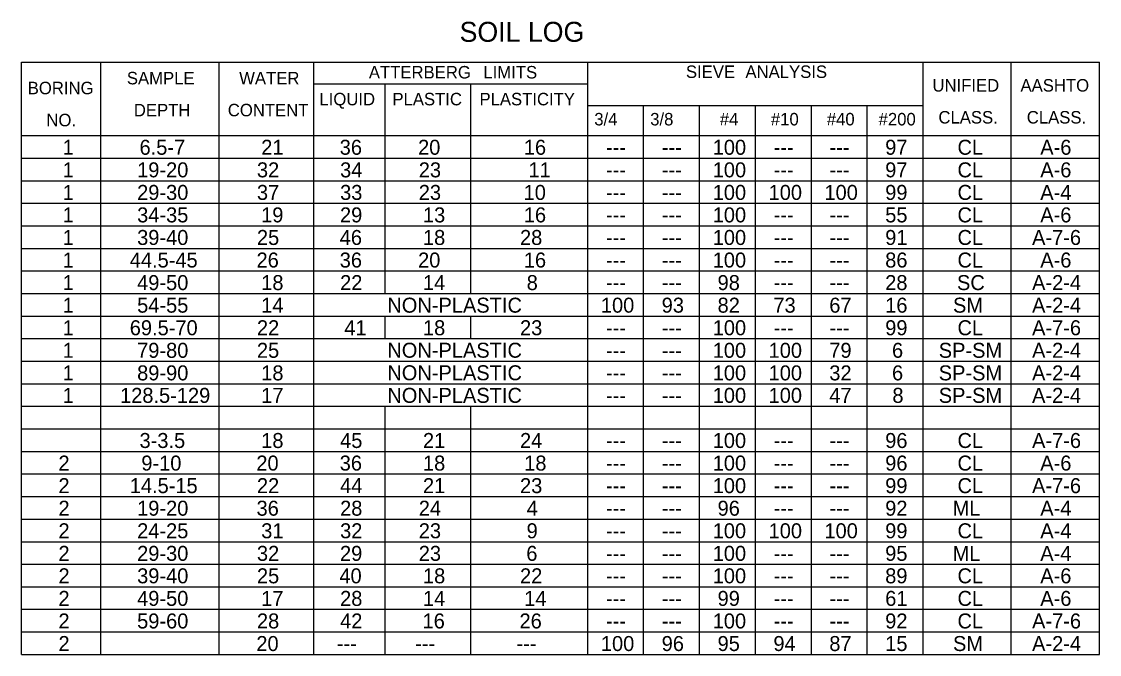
# Model space of a CAD drawing. Extents: x 1197542 to 1207464, y 185022 to 237324.
# Drawn here: x 1206798.9 to 1206906.8, y 185125.1 to 185188.5 of the extents above; entities that cross this region are included whole.
import ezdxf

# ---------------------------------------------------------------- set-up
doc = ezdxf.new("R2010")
doc.units = 0
doc.layers.add('R_No Plot', color=7, linetype='Continuous')

msp = doc.modelspace()

# ---------------------------------------------------------------- linework, layer by layer
at = {"layer": 'R_No Plot'}
for p, q in [((1206798.86, 185184.42), (1206798.86, 185184.42)), ((1206798.86, 185184.42), (1206906.83, 185184.42)), ((1206798.86, 185125.12), (1206798.86, 185184.42)), ((1206806.8, 185125.12), (1206806.8, 185184.42)), ((1206818.64, 185125.12), (1206818.64, 185184.42)), ((1206828.14, 185125.12), (1206828.14, 185184.42)), ((1206855.58, 185125.12), (1206855.58, 185184.42)), ((1206889.16, 185125.12), (1206889.16, 185184.42)), ((1206898, 185125.12), (1206898, 185184.42)), ((1206906.83, 185125.12), (1206906.83, 185184.42)), ((1206828.14, 185182.25), (1206855.58, 185182.25)), ((1206835.3, 185161.26), (1206835.3, 185182.25)), ((1206843.88, 185161.26), (1206843.88, 185182.25)), ((1206855.58, 185180.09), (1206889.16, 185180.09)), ((1206861.17, 185125.12), (1206861.17, 185180.09)), ((1206866.77, 185125.12), (1206866.77, 185180.09)), ((1206872.37, 185125.12), (1206872.37, 185180.09)), ((1206877.97, 185125.12), (1206877.97, 185180.09)), ((1206883.57, 185125.12), (1206883.57, 185180.09)), ((1206798.86, 185177.07), (1206906.83, 185177.07)), ((1206889.16, 185177.07), (1206906.83, 185177.07)), ((1206798.86, 185174.81), (1206906.83, 185174.81)), ((1206798.86, 185172.55), (1206906.83, 185172.55)), ((1206798.86, 185170.29), (1206906.83, 185170.29)), ((1206798.86, 185168.04), (1206906.83, 185168.04)), ((1206798.86, 185165.78), (1206906.83, 185165.78)), ((1206798.86, 185163.52), (1206906.83, 185163.52)), ((1206798.86, 185161.26), (1206906.83, 185161.26)), ((1206798.86, 185159), (1206906.83, 185159)), ((1206835.3, 185156.74), (1206835.3, 185159)), ((1206843.88, 185156.74), (1206843.88, 185159)), ((1206798.86, 185156.74), (1206906.83, 185156.74)), ((1206798.86, 185154.48), (1206906.83, 185154.48)), ((1206798.86, 185152.22), (1206906.83, 185152.22)), ((1206798.86, 185149.97), (1206906.83, 185149.97)), ((1206835.3, 185125.12), (1206835.3, 185149.97)), ((1206843.88, 185125.12), (1206843.88, 185149.97)), ((1206798.86, 185147.71), (1206906.83, 185147.71)), ((1206798.86, 185145.45), (1206906.83, 185145.45)), ((1206798.86, 185143.19), (1206906.83, 185143.19)), ((1206798.86, 185140.93), (1206906.83, 185140.93)), ((1206798.86, 185138.67), (1206906.83, 185138.67)), ((1206798.86, 185136.41), (1206906.83, 185136.41)), ((1206798.86, 185134.15), (1206906.83, 185134.15)), ((1206798.86, 185131.9), (1206906.83, 185131.9)), ((1206798.86, 185129.64), (1206906.83, 185129.64)), ((1206798.86, 185127.38), (1206906.83, 185127.38)), ((1206798.86, 185125.12), (1206906.83, 185125.12))]:
    msp.add_line(p, q, dxfattribs=at)

# ---------------------------------------------------------------- texts
for s, height, p in [('SOIL LOG', 2, (1206842.74, 185186.46)), ('ATTERBERG', 1.25, (1206833.65, 185182.79)), ('LIMITS', 1.25, (1206845.12, 185182.79)), ('SIEVE', 1.25, (1206865.41, 185182.84)), ('ANALYSIS', 1.25, (1206871.37, 185182.84)), ('SAMPLE', 1.25, (1206809.41, 185182.2)), ('WATER', 1.25, (1206820.66, 185182.2)), ('UNIFIED', 1.25, (1206890.1, 185181.48)), ('AASHTO', 1.25, (1206898.92, 185181.48)), ('BORING', 1.25, (1206799.48, 185181.21)), ('LIQUID', 1.25, (1206828.7, 185180.1)), ('PLASTIC', 1.25, (1206836.01, 185180.1)), ('PLASTICITY', 1.25, (1206844.73, 185180.1)), ('DEPTH', 1.25, (1206810.11, 185179)), ('CONTENT', 1.25, (1206819.52, 185179)), ('CLASS.', 1.25, (1206890.7, 185178.28)), ('CLASS.', 1.25, (1206899.55, 185178.28)), ('NO.', 1.25, (1206801.35, 185178)), ('3/4', 1.25, (1206856.23, 185178.09)), ('3/8', 1.25, (1206861.83, 185178.09)), ('#4', 1.25, (1206868.8, 185178.09)), ('#10', 1.25, (1206873.92, 185178.09)), ('#40', 1.25, (1206879.52, 185178.09)), ('#200', 1.25, (1206884.71, 185178.09)), ('1', 1.5, (1206802.98, 185175.15)), ('6.5-7', 1.5, (1206810.68, 185175.15)), ('21', 1.5, (1206822.87, 185175.15)), ('36', 1.5, (1206830.73, 185175.15)), ('20', 1.5, (1206838.58, 185175.15)), ('16', 1.5, (1206849.17, 185175.15)), ('100', 1.5, (1206868.09, 185175.15)), ('97', 1.5, (1206885.37, 185175.15)), ('CL', 1.5, (1206892.61, 185175.15)), ('A-6', 1.5, (1206900.9, 185175.15)), ('---', 1.5, (1206857.4, 185175.15)), ('---', 1.5, (1206863, 185175.15)), ('---', 1.5, (1206874.2, 185175.15)), ('---', 1.5, (1206879.8, 185175.15)), ('1', 1.5, (1206802.98, 185172.89)), ('19-20', 1.5, (1206810.44, 185172.89)), ('32', 1.5, (1206822.44, 185172.89)), ('34', 1.5, (1206830.77, 185172.89)), ('23', 1.5, (1206838.65, 185172.89)), ('11', 1.5, (1206849.64, 185172.89)), ('100', 1.5, (1206868.09, 185172.89)), ('97', 1.5, (1206885.37, 185172.89)), ('CL', 1.5, (1206892.61, 185172.89)), ('A-6', 1.5, (1206900.9, 185172.89)), ('---', 1.5, (1206857.4, 185172.89)), ('---', 1.5, (1206863, 185172.89)), ('---', 1.5, (1206874.2, 185172.89)), ('---', 1.5, (1206879.8, 185172.89)), ('1', 1.5, (1206802.98, 185170.63)), ('29-30', 1.5, (1206810.44, 185170.63)), ('37', 1.5, (1206822.44, 185170.63)), ('33', 1.5, (1206830.77, 185170.63)), ('23', 1.5, (1206838.65, 185170.63)), ('10', 1.5, (1206849.15, 185170.63)), ('100', 1.5, (1206868.09, 185170.63)), ('100', 1.5, (1206873.69, 185170.63)), ('100', 1.5, (1206879.28, 185170.63)), ('99', 1.5, (1206885.37, 185170.63)), ('CL', 1.5, (1206892.61, 185170.63)), ('A-4', 1.5, (1206900.9, 185170.63)), ('---', 1.5, (1206857.4, 185170.63)), ('---', 1.5, (1206863, 185170.63)), ('1', 1.5, (1206802.98, 185168.38)), ('34-35', 1.5, (1206810.44, 185168.38)), ('19', 1.5, (1206822.86, 185168.38)), ('29', 1.5, (1206830.76, 185168.38)), ('13', 1.5, (1206839.07, 185168.38)), ('16', 1.5, (1206849.17, 185168.38)), ('100', 1.5, (1206868.09, 185168.38)), ('55', 1.5, (1206885.37, 185168.38)), ('CL', 1.5, (1206892.61, 185168.38)), ('A-6', 1.5, (1206900.9, 185168.38)), ('---', 1.5, (1206857.4, 185168.38)), ('---', 1.5, (1206863, 185168.38)), ('---', 1.5, (1206874.2, 185168.38)), ('---', 1.5, (1206879.8, 185168.38)), ('1', 1.5, (1206802.98, 185166.12)), ('39-40', 1.5, (1206810.44, 185166.12)), ('25', 1.5, (1206822.44, 185166.12)), ('46', 1.5, (1206830.73, 185166.12)), ('18', 1.5, (1206839.07, 185166.12)), ('28', 1.5, (1206848.79, 185166.12)), ('100', 1.5, (1206868.09, 185166.12)), ('91', 1.5, (1206885.37, 185166.12)), ('CL', 1.5, (1206892.61, 185166.12)), ('A-7-6', 1.5, (1206900.08, 185166.12)), ('---', 1.5, (1206857.4, 185166.12)), ('---', 1.5, (1206863, 185166.12)), ('---', 1.5, (1206874.2, 185166.12)), ('---', 1.5, (1206879.8, 185166.12)), ('26', 1.5, (1206822.4, 185163.86)), ('36', 1.5, (1206830.73, 185163.86)), ('20', 1.5, (1206838.58, 185163.86)), ('16', 1.5, (1206849.17, 185163.86)), ('100', 1.5, (1206868.09, 185163.86)), ('86', 1.5, (1206885.37, 185163.86)), ('CL', 1.5, (1206892.61, 185163.86)), ('A-6', 1.5, (1206900.9, 185163.86)), ('1', 1.5, (1206802.98, 185163.86)), ('44.5-45', 1.5, (1206809.7, 185163.86)), ('---', 1.5, (1206857.4, 185163.86)), ('---', 1.5, (1206863, 185163.86)), ('---', 1.5, (1206874.2, 185163.86)), ('---', 1.5, (1206879.8, 185163.86)), ('1', 1.5, (1206802.98, 185161.6)), ('49-50', 1.5, (1206810.44, 185161.6)), ('18', 1.5, (1206822.87, 185161.6)), ('22', 1.5, (1206830.77, 185161.6)), ('14', 1.5, (1206839.07, 185161.6)), ('8', 1.5, (1206849.46, 185161.6)), ('---', 1.5, (1206857.4, 185161.6)), ('---', 1.5, (1206863, 185161.6)), ('98', 1.5, (1206868.58, 185161.6)), ('---', 1.5, (1206874.2, 185161.6)), ('---', 1.5, (1206879.8, 185161.6)), ('28', 1.5, (1206885.37, 185161.6)), ('SC', 1.5, (1206892.56, 185161.6)), ('A-2-4', 1.5, (1206900.08, 185161.6)), ('1', 1.5, (1206802.98, 185159.34)), ('54-55', 1.5, (1206810.44, 185159.34)), ('14', 1.5, (1206822.87, 185159.34)), ('NON-PLASTIC', 1.5, (1206835.5, 185159.34)), ('100', 1.5, (1206856.89, 185159.34)), ('93', 1.5, (1206862.98, 185159.34)), ('82', 1.5, (1206868.58, 185159.34)), ('73', 1.5, (1206874.17, 185159.34)), ('67', 1.5, (1206879.77, 185159.34)), ('16', 1.5, (1206885.37, 185159.34)), ('SM', 1.5, (1206892.16, 185159.34)), ('A-2-4', 1.5, (1206900.08, 185159.34)), ('1', 1.5, (1206802.98, 185157.08)), ('69.5-70', 1.5, (1206809.7, 185157.08)), ('22', 1.5, (1206822.44, 185157.08)), ('41', 1.5, (1206831.19, 185157.08)), ('18', 1.5, (1206839.07, 185157.08)), ('23', 1.5, (1206848.79, 185157.08)), ('100', 1.5, (1206868.09, 185157.08)), ('99', 1.5, (1206885.37, 185157.08)), ('CL', 1.5, (1206892.61, 185157.08)), ('A-7-6', 1.5, (1206900.08, 185157.08)), ('---', 1.5, (1206857.4, 185157.08)), ('---', 1.5, (1206863, 185157.08)), ('---', 1.5, (1206874.2, 185157.08)), ('---', 1.5, (1206879.8, 185157.08)), ('1', 1.5, (1206802.98, 185154.82)), ('79-80', 1.5, (1206810.44, 185154.82)), ('25', 1.5, (1206822.44, 185154.82)), ('NON-PLASTIC', 1.5, (1206835.5, 185154.83)), ('100', 1.5, (1206868.09, 185154.82)), ('100', 1.5, (1206873.69, 185154.82)), ('79', 1.5, (1206879.77, 185154.82)), ('6', 1.5, (1206886.05, 185154.82)), ('SP-SM', 1.5, (1206890.73, 185154.82)), ('A-2-4', 1.5, (1206900.08, 185154.82)), ('---', 1.5, (1206857.4, 185154.82)), ('---', 1.5, (1206863, 185154.82)), ('1', 1.5, (1206802.98, 185152.56)), ('89-90', 1.5, (1206810.44, 185152.56)), ('18', 1.5, (1206822.87, 185152.56)), ('NON-PLASTIC', 1.5, (1206835.5, 185152.57)), ('100', 1.5, (1206868.09, 185152.56)), ('100', 1.5, (1206873.69, 185152.56)), ('32', 1.5, (1206879.77, 185152.56)), ('6', 1.5, (1206886.05, 185152.56)), ('SP-SM', 1.5, (1206890.73, 185152.56)), ('A-2-4', 1.5, (1206900.08, 185152.56)), ('---', 1.5, (1206857.4, 185152.56)), ('---', 1.5, (1206863, 185152.56)), ('1', 1.5, (1206802.98, 185150.31)), ('128.5-129', 1.5, (1206808.73, 185150.31)), ('17', 1.5, (1206822.87, 185150.31)), ('NON-PLASTIC', 1.5, (1206835.5, 185150.31)), ('100', 1.5, (1206868.09, 185150.31)), ('100', 1.5, (1206873.69, 185150.31)), ('47', 1.5, (1206879.77, 185150.31)), ('8', 1.5, (1206886.09, 185150.31)), ('SP-SM', 1.5, (1206890.73, 185150.31)), ('A-2-4', 1.5, (1206900.08, 185150.31)), ('---', 1.5, (1206857.4, 185150.31)), ('---', 1.5, (1206863, 185150.31)), ('3-3.5', 1.5, (1206810.68, 185145.79)), ('18', 1.5, (1206822.87, 185145.79)), ('45', 1.5, (1206830.77, 185145.79)), ('21', 1.5, (1206839.07, 185145.79)), ('24', 1.5, (1206848.79, 185145.79)), ('100', 1.5, (1206868.09, 185145.79)), ('96', 1.5, (1206885.37, 185145.79)), ('CL', 1.5, (1206892.61, 185145.79)), ('A-7-6', 1.5, (1206900.08, 185145.79)), ('---', 1.5, (1206857.4, 185145.79)), ('---', 1.5, (1206863, 185145.79)), ('---', 1.5, (1206874.2, 185145.79)), ('---', 1.5, (1206879.8, 185145.79)), ('2', 1.5, (1206802.56, 185143.53)), ('9-10', 1.5, (1206810.86, 185143.53)), ('20', 1.5, (1206822.38, 185143.53)), ('36', 1.5, (1206830.73, 185143.53)), ('18', 1.5, (1206839.07, 185143.53)), ('18', 1.5, (1206849.21, 185143.53)), ('100', 1.5, (1206868.09, 185143.53)), ('96', 1.5, (1206885.37, 185143.53)), ('CL', 1.5, (1206892.61, 185143.53)), ('A-6', 1.5, (1206900.9, 185143.53)), ('---', 1.5, (1206857.4, 185143.53)), ('---', 1.5, (1206863, 185143.53)), ('---', 1.5, (1206874.2, 185143.53)), ('---', 1.5, (1206879.8, 185143.53)), ('2', 1.5, (1206802.56, 185141.27)), ('14.5-15', 1.5, (1206809.7, 185141.27)), ('22', 1.5, (1206822.44, 185141.27)), ('44', 1.5, (1206830.77, 185141.27)), ('21', 1.5, (1206839.07, 185141.27)), ('23', 1.5, (1206848.79, 185141.27)), ('100', 1.5, (1206868.09, 185141.27)), ('99', 1.5, (1206885.37, 185141.27)), ('CL', 1.5, (1206892.61, 185141.27)), ('A-7-6', 1.5, (1206900.08, 185141.27)), ('---', 1.5, (1206857.4, 185141.27)), ('---', 1.5, (1206863, 185141.27)), ('---', 1.5, (1206874.2, 185141.27)), ('---', 1.5, (1206879.8, 185141.27)), ('2', 1.5, (1206802.56, 185139.01)), ('19-20', 1.5, (1206810.44, 185139.01)), ('36', 1.5, (1206822.4, 185139.01)), ('28', 1.5, (1206830.77, 185139.01)), ('24', 1.5, (1206838.65, 185139.01)), ('4', 1.5, (1206849.46, 185139.01)), ('---', 1.5, (1206857.4, 185139.01)), ('---', 1.5, (1206863, 185139.01)), ('96', 1.5, (1206868.58, 185139.01)), ('---', 1.5, (1206874.2, 185139.01)), ('---', 1.5, (1206879.8, 185139.01)), ('92', 1.5, (1206885.37, 185139.01)), ('ML', 1.5, (1206892.12, 185139.01)), ('A-4', 1.5, (1206900.9, 185139.01)), ('2', 1.5, (1206802.56, 185136.75)), ('24-25', 1.5, (1206810.44, 185136.75)), ('31', 1.5, (1206822.87, 185136.75)), ('32', 1.5, (1206830.77, 185136.75)), ('23', 1.5, (1206838.65, 185136.75)), ('9', 1.5, (1206849.45, 185136.75)), ('---', 1.5, (1206857.4, 185136.75)), ('---', 1.5, (1206863, 185136.75)), ('100', 1.5, (1206868.09, 185136.75)), ('100', 1.5, (1206873.69, 185136.75)), ('100', 1.5, (1206879.28, 185136.75)), ('99', 1.5, (1206885.37, 185136.75)), ('CL', 1.5, (1206892.61, 185136.75)), ('A-4', 1.5, (1206900.9, 185136.75)), ('2', 1.5, (1206802.56, 185134.49)), ('29-30', 1.5, (1206810.44, 185134.49)), ('32', 1.5, (1206822.44, 185134.49)), ('29', 1.5, (1206830.76, 185134.49)), ('23', 1.5, (1206838.65, 185134.49)), ('6', 1.5, (1206849.42, 185134.49)), ('---', 1.5, (1206857.4, 185134.49)), ('---', 1.5, (1206863, 185134.49)), ('100', 1.5, (1206868.09, 185134.49)), ('---', 1.5, (1206874.2, 185134.49)), ('---', 1.5, (1206879.8, 185134.49)), ('95', 1.5, (1206885.37, 185134.49)), ('ML', 1.5, (1206892.12, 185134.49)), ('A-4', 1.5, (1206900.9, 185134.49)), ('2', 1.5, (1206802.56, 185132.24)), ('39-40', 1.5, (1206810.44, 185132.24)), ('25', 1.5, (1206822.44, 185132.24)), ('40', 1.5, (1206830.7, 185132.24)), ('18', 1.5, (1206839.07, 185132.24)), ('22', 1.5, (1206848.79, 185132.24)), ('100', 1.5, (1206868.09, 185132.24)), ('89', 1.5, (1206885.37, 185132.24)), ('CL', 1.5, (1206892.61, 185132.24)), ('A-6', 1.5, (1206900.9, 185132.24)), ('---', 1.5, (1206857.4, 185132.24)), ('---', 1.5, (1206863, 185132.24)), ('---', 1.5, (1206874.2, 185132.24)), ('---', 1.5, (1206879.8, 185132.24)), ('2', 1.5, (1206802.56, 185129.98)), ('49-50', 1.5, (1206810.44, 185129.98)), ('17', 1.5, (1206822.87, 185129.98)), ('28', 1.5, (1206830.77, 185129.98)), ('14', 1.5, (1206839.07, 185129.98)), ('14', 1.5, (1206849.21, 185129.98)), ('99', 1.5, (1206868.58, 185129.98)), ('61', 1.5, (1206885.37, 185129.98)), ('CL', 1.5, (1206892.61, 185129.98)), ('A-6', 1.5, (1206900.9, 185129.98)), ('---', 1.5, (1206857.4, 185129.98)), ('---', 1.5, (1206863, 185129.98)), ('---', 1.5, (1206874.2, 185129.98)), ('---', 1.5, (1206879.8, 185129.98)), ('2', 1.5, (1206802.56, 185127.72)), ('59-60', 1.5, (1206810.44, 185127.72)), ('28', 1.5, (1206822.44, 185127.72)), ('42', 1.5, (1206830.77, 185127.72)), ('16', 1.5, (1206839.03, 185127.72)), ('26', 1.5, (1206848.74, 185127.72)), ('100', 1.5, (1206868.09, 185127.72)), ('92', 1.5, (1206885.37, 185127.72)), ('CL', 1.5, (1206892.61, 185127.72)), ('A-7-6', 1.5, (1206900.08, 185127.72)), ('---', 1.5, (1206857.4, 185127.72)), ('---', 1.5, (1206863, 185127.72)), ('---', 1.5, (1206874.2, 185127.72)), ('---', 1.5, (1206879.8, 185127.72)), ('2', 1.5, (1206802.56, 185125.46)), ('20', 1.5, (1206822.38, 185125.46)), ('100', 1.5, (1206856.89, 185125.46)), ('96', 1.5, (1206862.98, 185125.46)), ('95', 1.5, (1206868.58, 185125.46)), ('94', 1.5, (1206874.17, 185125.46)), ('87', 1.5, (1206879.77, 185125.46)), ('15', 1.5, (1206885.37, 185125.46)), ('SM', 1.5, (1206892.16, 185125.46)), ('A-2-4', 1.5, (1206900.08, 185125.46)), ('---', 1.5, (1206830.44, 185125.46)), ('---', 1.5, (1206838.29, 185125.46)), ('---', 1.5, (1206848.43, 185125.46))]:
    msp.add_text(s, height=height, dxfattribs=at).set_placement(p)

doc.saveas('drawing.dxf')
